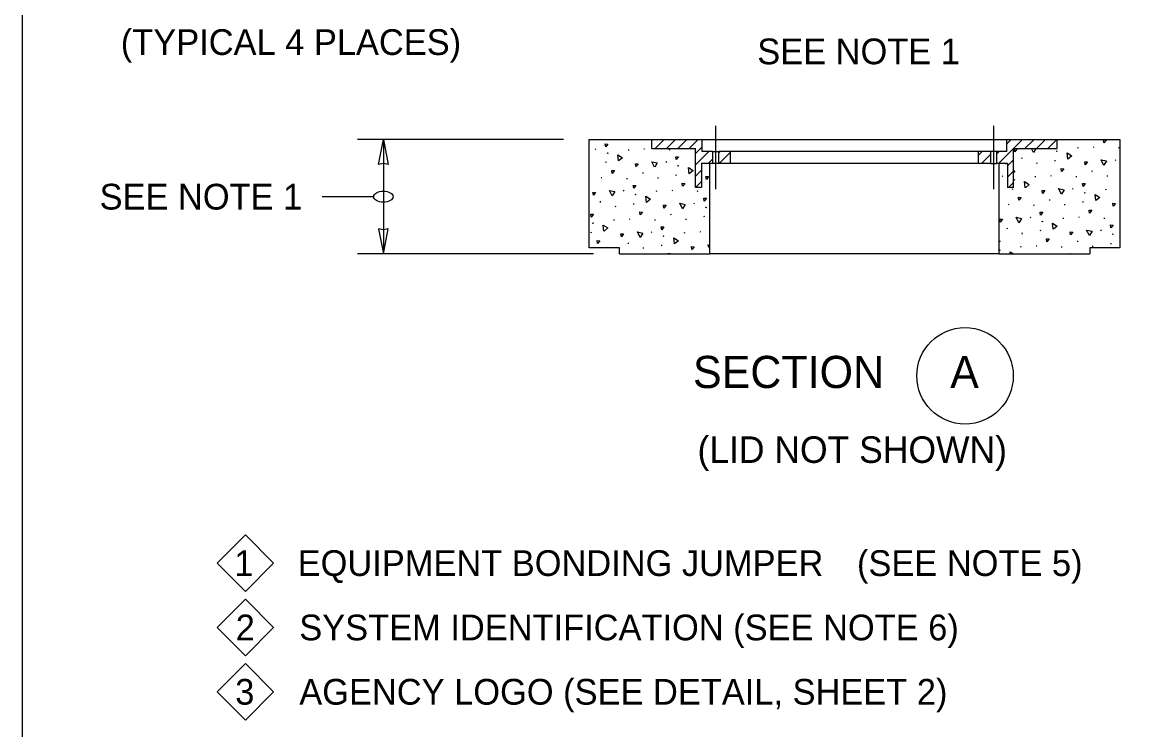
# Model space of a CAD drawing. Extents: x 99862 to 103151, y 100000 to 105076.
# Drawn here: x 99862 to 100555, y 101057 to 101497 of the extents above; entities that cross this region are included whole.
import ezdxf

# ---------------------------------------------------------------- set-up
doc = ezdxf.new("R2010")
doc.units = 0
for name, color, linetype in [('Level 1', 7, 'Continuous'), ('Level 10', 7, 'Continuous'), ('Level 11', 7, 'Continuous'), ('Level 15', 7, 'Continuous'), ('Level 20', 7, 'Continuous')]:
    doc.layers.add(name, color=color, linetype=linetype)

msp = doc.modelspace()

# ---------------------------------------------------------------- linework, layer by layer
at = {"layer": 'Level 1'}
msp.add_lwpolyline([(99862, 99999.5), (103151, 99999.5), (103151, 102075.5), (99862, 102075.5)], close=True, dxfattribs=at)
at = {"layer": 'Level 10'}
for p, q in [((100214.54, 101356.86), (100214.54, 101424.36)), ((100214.54, 101424.36), (100253.45, 101424.36)), ((100284.86, 101424.36), (100474.23, 101424.36)), ((100505.64, 101424.36), (100544.54, 101424.36)), ((100544.54, 101424.36), (100544.54, 101356.86)), ((100289.54, 101353.11), (100289.54, 101409.36)), ((100469.54, 101353.11), (100469.54, 101409.36)), ((100233.29, 101356.86), (100214.54, 101356.86)), ((100233.29, 101353.11), (100233.29, 101356.86)), ((100544.54, 101356.86), (100525.79, 101356.86)), ((100525.79, 101356.86), (100525.79, 101353.11)), ((100233.29, 101353.11), (100289.54, 101353.11)), ((100469.54, 101353.11), (100289.54, 101353.11)), ((100469.54, 101353.11), (100525.79, 101353.11))]:
    msp.add_line(p, q, dxfattribs=at)
at = {"layer": 'Level 11'}
for p, q in [((100253.45, 101418.74), (100253.45, 101424.36)), ((100253.45, 101424.36), (100284.86, 101424.36)), ((100253.45, 101423.76), (100254.06, 101424.36)), ((100255.5, 101418.74), (100261.13, 101424.36)), ((100262.57, 101418.74), (100268.2, 101424.36)), ((100269.64, 101418.74), (100275.27, 101424.36)), ((100276.72, 101418.74), (100282.34, 101424.36)), ((100280.64, 101415.59), (100284.86, 101419.81)), ((100284.86, 101416.86), (100284.86, 101424.36)), ((100474.23, 101416.86), (100474.23, 101424.36)), ((100474.23, 101424.36), (100505.64, 101424.36)), ((100474.23, 101421.56), (100477.04, 101424.36)), ((100478.48, 101418.74), (100484.11, 101424.36)), ((100485.55, 101418.74), (100491.18, 101424.36)), ((100492.63, 101418.74), (100498.25, 101424.36)), ((100499.7, 101418.74), (100505.32, 101424.36)), ((100505.64, 101418.74), (100505.64, 101424.36)), ((100518.63, 101418.62), (100518.52, 101419.27)), ((100527.92, 101419.74), (100528.36, 101419.56)), ((100544.07, 101418.67), (100543.96, 101419.31)), ((100218.34, 101418.48), (100218.73, 101418.02)), ((100225.5, 101416.01), (100225.94, 101415.83)), ((100225.8, 101416.03), (100226.25, 101415.85)), ((100239.22, 101417.46), (100239.11, 101418.11)), ((100248.51, 101418.58), (100248.95, 101418.4)), ((100253.45, 101418.74), (100280.64, 101418.74)), ((100264.66, 101417.51), (100264.54, 101418.15)), ((100280.64, 101394.36), (100280.64, 101418.74)), ((100280.64, 101408.52), (100288.98, 101416.86)), ((100284.86, 101416.86), (100284.86, 101416.86)), ((100291.18, 101416.86), (100284.86, 101416.86)), ((100288.55, 101409.36), (100291.18, 101411.99)), ((100291.18, 101416.86), (100291.18, 101409.36)), ((100291.18, 101416.86), (100294.93, 101416.86)), ((100294.93, 101416.86), (100294.93, 101416.86)), ((100294.93, 101416.86), (100294.93, 101409.36)), ((100302.43, 101416.86), (100294.93, 101416.86)), ((100294.93, 101415.89), (100295.9, 101416.86)), ((100295.47, 101409.36), (100302.43, 101416.32)), ((100456.65, 101416.86), (100302.43, 101416.86)), ((100302.43, 101409.36), (100302.43, 101416.86)), ((100464.15, 101416.86), (100456.65, 101416.86)), ((100456.65, 101409.36), (100456.65, 101416.86)), ((100456.65, 101414.57), (100458.94, 101416.86)), ((100458.51, 101409.36), (100464.15, 101415)), ((100464.15, 101416.86), (100464.15, 101409.36)), ((100467.9, 101416.86), (100464.15, 101416.86)), ((100467.9, 101416.86), (100467.9, 101416.86)), ((100474.23, 101416.86), (100467.9, 101416.86)), ((100467.9, 101416.86), (100467.9, 101409.36)), ((100467.9, 101415.23), (100469.54, 101416.86)), ((100469.11, 101409.36), (100478.45, 101418.7)), ((100478.45, 101418.74), (100505.64, 101418.74)), ((100478.45, 101394.36), (100478.45, 101418.74)), ((100483.7, 101412.18), (100483.58, 101412.82)), ((100504.91, 101417.17), (100505.36, 101416.99)), ((100505.22, 101417.19), (100505.66, 101417.01)), ((100225, 101409.72), (100224.89, 101410.36)), ((100262.19, 101410.53), (100262.58, 101410.07)), ((100269.34, 101408.06), (100269.79, 101407.87)), ((100269.65, 101408.08), (100270.09, 101407.9)), ((100280.64, 101401.45), (100284.39, 101405.2)), ((100284.39, 101409.36), (100284.39, 101394.36)), ((100289.54, 101409.36), (100284.39, 101409.36)), ((100291.18, 101409.36), (100289.54, 101409.36)), ((100294.93, 101409.36), (100291.18, 101409.36)), ((100302.43, 101409.36), (100294.93, 101409.36)), ((100456.65, 101409.36), (100302.43, 101409.36)), ((100302.43, 101409.36), (100302.43, 101409.36)), ((100456.65, 101409.36), (100456.65, 101409.36)), ((100464.15, 101409.36), (100456.65, 101409.36)), ((100464.15, 101409.36), (100467.9, 101409.36)), ((100469.54, 101409.36), (100467.9, 101409.36)), ((100474.7, 101409.36), (100469.54, 101409.36)), ((100473.78, 101408.78), (100473.67, 101409.36)), ((100474.7, 101407.88), (100478.45, 101411.63)), ((100474.7, 101409.36), (100474.7, 101394.36)), ((100493.04, 101409.16), (100492.93, 101409.81)), ((100504.41, 101410.88), (100504.3, 101411.52)), ((100541.6, 101411.69), (100542, 101411.23)), ((100222.06, 101400.74), (100222.5, 101400.56)), ((100238.21, 101399.67), (100238.09, 101400.31)), ((100248.13, 101403.06), (100248.01, 101403.71)), ((100257.47, 101400.05), (100257.36, 101400.69)), ((100268.85, 101401.76), (100268.73, 101402.41)), ((100280.64, 101394.37), (100284.39, 101398.12)), ((100471.31, 101401.8), (100471.7, 101401.35)), ((100474.7, 101400.81), (100478.45, 101404.56)), ((100478.46, 101399.33), (100478.91, 101399.15)), ((100478.77, 101399.35), (100479.21, 101399.17)), ((100492.19, 101400.78), (100492.07, 101401.43)), ((100501.47, 101401.9), (100501.92, 101401.72)), ((100517.62, 101400.83), (100517.51, 101401.47)), ((100527.54, 101404.22), (100527.43, 101404.87)), ((100536.89, 101401.21), (100536.77, 101401.85)), ((100235.74, 101392.69), (100236.13, 101392.23)), ((100256.62, 101391.67), (100256.5, 101392.31)), ((100265.9, 101392.79), (100266.35, 101392.61)), ((100284.39, 101394.36), (100280.64, 101394.36)), ((100282.05, 101391.71), (100281.94, 101392.36)), ((100284.39, 101394.36), (100284.39, 101394.36)), ((100474.7, 101394.36), (100474.7, 101394.36)), ((100478.45, 101394.36), (100474.7, 101394.36)), ((100475.32, 101394.36), (100478.45, 101397.49)), ((100477.97, 101393.04), (100477.85, 101393.68)), ((100515.16, 101393.85), (100515.55, 101393.39)), ((100522.31, 101391.38), (100522.75, 101391.19)), ((100522.62, 101391.4), (100523.06, 101391.22)), ((100536.03, 101392.83), (100535.92, 101393.48)), ((100221.68, 101385.22), (100221.56, 101385.87)), ((100242.4, 101383.92), (100242.28, 101384.57)), ((100242.89, 101390.22), (100243.34, 101390.03)), ((100243.2, 101390.24), (100243.64, 101390.06)), ((100279.59, 101384.74), (100279.98, 101384.28)), ((100501.09, 101386.38), (100500.98, 101387.03)), ((100521.81, 101385.09), (100521.7, 101385.73)), ((100231.02, 101382.21), (100230.91, 101382.85)), ((100265.52, 101377.27), (100265.41, 101377.92)), ((100286.74, 101382.26), (100287.19, 101382.08)), ((100287.05, 101382.29), (100287.49, 101382.1)), ((100475.02, 101384.06), (100475.47, 101383.88)), ((100491.17, 101382.99), (100491.06, 101383.63)), ((100510.44, 101383.37), (100510.32, 101384.01)), ((100216.45, 101372.38), (100216.89, 101372.19)), ((100216.75, 101372.4), (100217.2, 101372.22)), ((100230.17, 101373.83), (100230.05, 101374.47)), ((100239.45, 101374.95), (100239.9, 101374.77)), ((100255.6, 101373.87), (100255.49, 101374.52)), ((100274.87, 101374.26), (100274.75, 101374.9)), ((100286.24, 101375.97), (100286.13, 101376.62)), ((100488.71, 101376.01), (100489.1, 101375.55)), ((100495.86, 101373.54), (100496.3, 101373.35)), ((100496.17, 101373.56), (100496.61, 101373.38)), ((100509.58, 101374.99), (100509.47, 101375.64)), ((100518.87, 101376.11), (100519.31, 101375.93)), ((100535.02, 101375.04), (100534.91, 101375.68)), ((100215.95, 101366.08), (100215.83, 101366.73)), ((100253.14, 101366.9), (100253.53, 101366.44)), ((100260.29, 101364.42), (100260.74, 101364.24)), ((100260.6, 101364.45), (100261.04, 101364.26)), ((100274.01, 101365.88), (100273.9, 101366.52)), ((100283.3, 101367), (100283.74, 101366.82)), ((100474.64, 101368.54), (100474.53, 101369.19)), ((100483.99, 101365.53), (100483.87, 101366.17)), ((100495.36, 101367.25), (100495.25, 101367.89)), ((100532.55, 101368.06), (100532.94, 101367.6)), ((100539.71, 101365.58), (100540.15, 101365.4)), ((100540.01, 101365.61), (100540.46, 101365.42)), ((100239.08, 101359.43), (100238.96, 101360.08)), ((100248.42, 101356.42), (100248.31, 101357.06)), ((100259.79, 101358.13), (100259.68, 101358.78)), ((100483.13, 101357.15), (100483.02, 101357.8)), ((100492.42, 101358.27), (100492.86, 101358.09)), ((100508.57, 101357.2), (100508.46, 101357.84)), ((100518.49, 101360.59), (100518.38, 101361.24)), ((100527.83, 101357.58), (100527.72, 101358.22)), ((100539.21, 101359.29), (100539.09, 101359.94)), ((100469.54, 101355.64), (100469.86, 101355.51)), ((100469.72, 101355.72), (100470.16, 101355.54))]:
    msp.add_line(p, q, dxfattribs=at)
for points in [[(100224.83, 101419.74), (100224.56, 101421.56), (100226.23, 101421.48), (100224.83, 101419.74)], [(100505.64, 101422.64), (100505.64, 101422.64), (100505.64, 101422.64)], [(100534.69, 101422.22), (100534.42, 101424.05), (100536.08, 101423.96), (100534.69, 101422.22)], [(100232.77, 101410.94), (100232.36, 101414.76), (100235.27, 101412.95), (100232.83, 101410.98)], [(100268.68, 101411.78), (100268.41, 101413.61), (100270.07, 101413.53), (100268.68, 101411.78)], [(100479.16, 101416.55), (100478.89, 101418.38), (100480.55, 101418.29), (100479.16, 101416.55)], [(100490.8, 101416.14), (100489.52, 101418.74)], [(100492.38, 101418.74), (100490.84, 101416.19)], [(100512.19, 101412.1), (100511.78, 101415.92), (100514.69, 101414.11), (100512.24, 101412.14)], [(100228.82, 101403.22), (100228.55, 101405.04), (100230.22, 101404.96), (100228.82, 101403.22)], [(100243.59, 101407.43), (100243.32, 101409.26), (100244.98, 101409.18), (100243.59, 101407.43)], [(100255.23, 101407.02), (100253.54, 101410.47), (100256.89, 101409.77), (100255.27, 101407.08)], [(100276.62, 101402.99), (100276.21, 101406.81), (100279.12, 101405), (100276.67, 101403.03)], [(100508.24, 101404.38), (100507.97, 101406.21), (100509.63, 101406.12), (100508.24, 101404.38)], [(100523, 101408.6), (100522.73, 101410.42), (100524.4, 101410.34), (100523, 101408.6)], [(100534.64, 101408.18), (100532.95, 101411.64), (100536.31, 101410.93), (100534.68, 101408.24)], [(100287.43, 101399.48), (100287.17, 101401.31), (100288.83, 101401.23), (100287.43, 101399.48)], [(100478.45, 101404.84), (100479.19, 101404.8), (100478.45, 101403.87)], [(100217.14, 101389.59), (100216.87, 101391.42), (100218.53, 101391.34), (100217.14, 101389.59)], [(100228.78, 101389.18), (100227.09, 101392.63), (100230.44, 101391.93), (100228.82, 101389.24)], [(100242.23, 101393.94), (100241.96, 101395.77), (100243.62, 101395.69), (100242.23, 101393.94)], [(100272.67, 101395.26), (100272.4, 101397.09), (100274.06, 101397.01), (100272.67, 101395.26)], [(100485.74, 101394.26), (100485.33, 101398.08), (100488.24, 101396.27), (100485.79, 101394.3)], [(100496.55, 101390.76), (100496.29, 101392.58), (100497.95, 101392.5), (100496.55, 101390.76)], [(100508.2, 101390.34), (100506.5, 101393.8), (100509.86, 101393.09), (100508.23, 101390.4)], [(100521.64, 101395.1), (100521.37, 101396.93), (100523.04, 101396.85), (100521.64, 101395.1)], [(100250.17, 101385.15), (100249.76, 101388.97), (100252.67, 101387.16), (100250.22, 101385.19)], [(100272.63, 101381.23), (100270.94, 101384.68), (100274.29, 101383.97), (100272.67, 101381.28)], [(100286.07, 101385.99), (100285.81, 101387.82), (100287.47, 101387.74), (100286.07, 101385.99)], [(100481.79, 101386.54), (100481.52, 101388.37), (100483.18, 101388.28), (100481.79, 101386.54)], [(100529.58, 101386.31), (100529.17, 101390.13), (100532.08, 101388.32), (100529.64, 101386.35)], [(100540.4, 101382.8), (100540.13, 101384.63), (100541.79, 101384.55), (100540.4, 101382.8)], [(100215.78, 101376.1), (100215.51, 101377.93), (100217.17, 101377.85), (100215.78, 101376.1)], [(100246.22, 101377.42), (100245.95, 101379.25), (100247.61, 101379.17), (100246.22, 101377.42)], [(100260.99, 101381.64), (100260.72, 101383.47), (100262.38, 101383.39), (100260.99, 101381.64)], [(100495.19, 101377.26), (100494.93, 101379.09), (100496.59, 101379.01), (100495.19, 101377.26)], [(100525.63, 101378.59), (100525.37, 101380.41), (100527.03, 101380.33), (100525.63, 101378.59)], [(100223.72, 101367.31), (100223.31, 101371.13), (100226.22, 101369.32), (100223.77, 101367.35)], [(100470.11, 101372.92), (100469.84, 101374.74), (100471.5, 101374.66), (100470.11, 101372.92)], [(100481.75, 101372.5), (100480.06, 101375.96), (100483.41, 101375.25), (100481.79, 101372.56)], [(100503.13, 101368.47), (100502.73, 101372.29), (100505.64, 101370.48), (100503.19, 101368.51)], [(100539.04, 101369.31), (100538.77, 101371.14), (100540.43, 101371.06), (100539.04, 101369.31)], [(100234.54, 101363.8), (100234.27, 101365.63), (100235.93, 101365.55), (100234.54, 101363.8)], [(100246.18, 101363.39), (100244.49, 101366.84), (100247.84, 101366.13), (100246.22, 101363.44)], [(100259.63, 101368.15), (100259.36, 101369.98), (100261.02, 101369.9), (100259.63, 101368.15)], [(100513.95, 101364.96), (100513.68, 101366.79), (100515.35, 101366.71), (100513.95, 101364.96)], [(100525.59, 101364.55), (100523.9, 101368), (100527.26, 101367.29), (100525.63, 101364.61)], [(100219.77, 101359.58), (100219.5, 101361.41), (100221.16, 101361.33), (100219.77, 101359.58)], [(100267.57, 101359.36), (100267.16, 101363.18), (100270.07, 101361.37), (100267.62, 101359.39)], [(100278.38, 101355.85), (100278.11, 101357.68), (100279.78, 101357.59), (100278.38, 101355.85)], [(100289.54, 101356.42), (100288.33, 101358.89), (100289.54, 101358.63)], [(100469.54, 101361.2), (100470.14, 101361.17), (100469.54, 101360.42)], [(100499.19, 101360.75), (100498.92, 101362.57), (100500.58, 101362.49), (100499.19, 101360.75)], [(100263.4, 101353.11), (100263.35, 101353.46), (100265.01, 101353.38), (100264.8, 101353.11)], [(100476.42, 101353.11), (100476.28, 101354.45), (100478.43, 101353.11)], [(100512.35, 101353.11), (100512.32, 101353.3), (100513.99, 101353.22), (100513.9, 101353.11)]]:
    msp.add_lwpolyline(points, dxfattribs=at)
at = {"layer": 'Level 15'}
for p, q in [((100293.06, 101432.86), (100293.06, 101393.36)), ((100466.03, 101432.86), (100466.03, 101393.36)), ((100198.54, 101424.36), (100070.54, 101424.36)), ((100086.54, 101424.36), (100086.54, 101353.11)), ((100064.54, 101388.74), (100048.54, 101388.74)), ((100080.54, 101388.74), (100064.54, 101388.74)), ((100217.29, 101353.11), (100070.54, 101353.11))]:
    msp.add_line(p, q, dxfattribs=at)
for points in [[(100086.54, 101424.36), (100089.63, 101408.64), (100086.54, 101409.36), (100083.46, 101408.64)], [(100086.54, 101353.11), (100089.63, 101368.84), (100086.54, 101368.11), (100083.46, 101368.84)]]:
    msp.add_lwpolyline(points, close=True, dxfattribs=at)
msp.add_ellipse((100086.54, 101388.74), major_axis=(-6, 0), ratio=0.57735, dxfattribs=at)
at = {"layer": 'Level 20'}
for points in [[(100000.71, 101178.49), (100018.27, 101160.94), (100000.71, 101143.39), (99983.16, 101160.94)], [(100000.71, 101138.49), (100018.27, 101120.94), (100000.71, 101103.39), (99983.16, 101120.94)], [(100000.71, 101098.49), (100018.27, 101080.94), (100000.71, 101063.39), (99983.16, 101080.94)]]:
    msp.add_lwpolyline(points, close=True, dxfattribs=at)
msp.add_circle((100448.27, 101277.38), 30, dxfattribs=at)

# ---------------------------------------------------------------- texts
for s, height, p in [('(TYPICAL 4 PLACES)', 16, (99923.26, 101476.83)), ('SEE NOTE 1', 16, (100319.07, 101471.05)), ('SEE NOTE 1', 16, (99910.07, 101380.74)), ('SECTION', 20, (100279.08, 101269.77)), ('A', 20, (100439.03, 101269.76)), ('(LID NOT SHOWN)', 16.5, (100281.9, 101223.24)), ('(SEE NOTE 5)', 16, (100381.07, 101152.94)), ('1', 16, (99993.85, 101152.94)), ('EQUIPMENT BONDING JUMPER', 16, (100033.27, 101152.94)), ('2', 16, (99994.73, 101112.94)), ('SYSTEM IDENTIFICATION (SEE NOTE 6)', 16, (100034.27, 101112.94)), ('3', 16, (99994.42, 101072.94)), ('AGENCY LOGO (SEE DETAIL, SHEET 2)', 16, (100034.27, 101072.94))]:
    msp.add_text(s, height=height, dxfattribs=at).set_placement(p)

doc.saveas('drawing.dxf')
